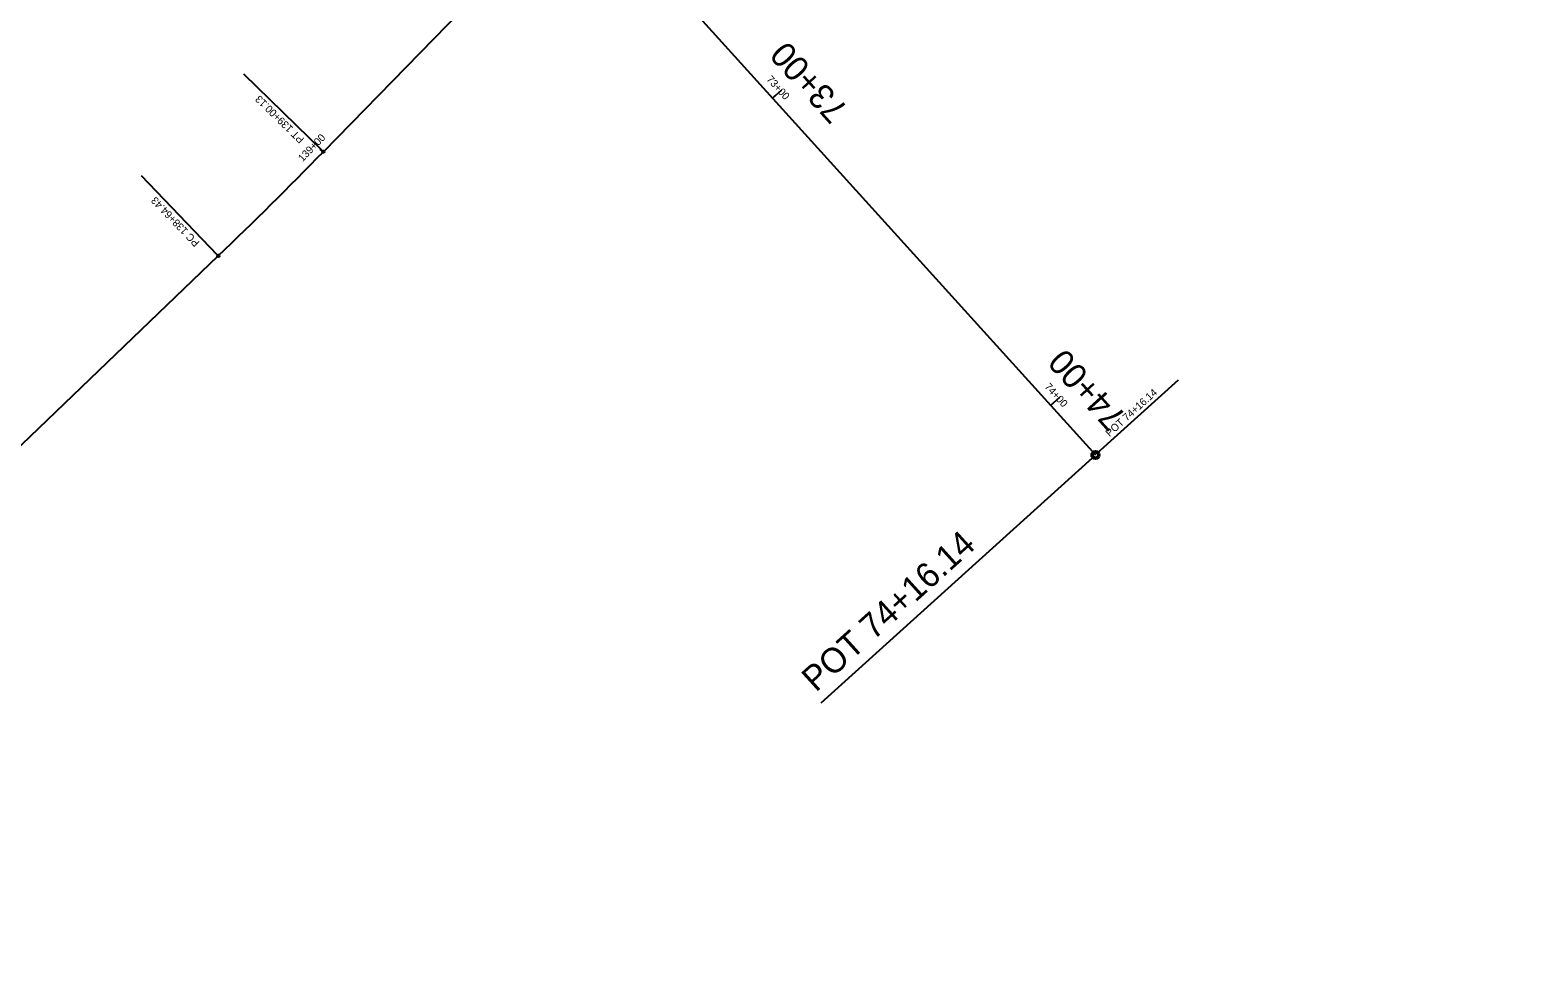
# Model space of a CAD drawing. Extents: x 2252491 to 2257126, y 13788370 to 13792743.
# Drawn here: x 2255321.9 to 2255685.6, y 13791067.5 to 13791291.8 of the extents above; entities that cross this region are included whole.
import ezdxf

# ---------------------------------------------------------------- set-up
doc = ezdxf.new("R2010")
doc.units = 0
for name, color, linetype in [('D_ALIGN_1', 7, 'Continuous'), ('D_ALIGN_ANNO_1', 7, 'Continuous'), ('D_ALIGN_ANNO_DOVE_CROSSING', 7, 'Continuous'), ('D_ALIGN_ANNO_DOVE_CROSSING_30', 7, 'Continuous'), ('D_ALIGN_DOVE_CROSSING', 7, 'Continuous')]:
    doc.layers.add(name, color=color, linetype=linetype)

msp = doc.modelspace()

# ---------------------------------------------------------------- linework, layer by layer
at = {"layer": 'D_ALIGN_1'}
for p, q in [((2255392.67, 13791262.46), (2255685.62, 13791562.66)), ((2255062.92, 13790944.99), (2255367.32, 13791237.32))]:
    msp.add_line(p, q, dxfattribs=at)
msp.add_arc((2254605.4, 13792030.71), 1100, 313.84074, 315.70035, dxfattribs=at)
at = {"layer": 'D_ALIGN_ANNO_1'}
for p, q in [((2255392.45, 13791262.67), (2255373.51, 13791281.15)), ((2255392.58, 13791262.37), (2255391.93, 13791263)), ((2255367.11, 13791237.53), (2255348.78, 13791256.62))]:
    msp.add_line(p, q, dxfattribs=at)
for centre in [(2255392.67, 13791262.46), (2255367.32, 13791237.32)]:
    msp.add_circle(centre, 0.3, dxfattribs=at)
at = {"layer": 'D_ALIGN_ANNO_DOVE_CROSSING'}
for p, q in [((2255501, 13791275.41), (2255503.22, 13791277.42)), ((2255568.08, 13791201.25), (2255570.3, 13791203.26)), ((2255512.78, 13791129.47), (2255578.17, 13791188.61))]:
    msp.add_line(p, q, dxfattribs=at)
msp.add_circle((2255578.91, 13791189.28), 1, dxfattribs=at)
at = {"layer": 'D_ALIGN_ANNO_DOVE_CROSSING_30'}
for p, q in [((2255501, 13791275.41), (2255501.66, 13791276.01)), ((2255579.35, 13791189.68), (2255598.97, 13791207.43)), ((2255568.08, 13791201.25), (2255568.75, 13791201.85))]:
    msp.add_line(p, q, dxfattribs=at)
msp.add_circle((2255578.91, 13791189.28), 0.6, dxfattribs=at)
at = {"layer": 'D_ALIGN_DOVE_CROSSING'}
msp.add_line((2255410.82, 13791375.1), (2255578.91, 13791189.28), dxfattribs=at)

# ---------------------------------------------------------------- texts
at = {"layer": 'D_ALIGN_ANNO_1'}
for s, rotation, p in [('PT 139+00.13', 135.7003, (2255388.17, 13791265.59)), ('139+00', 45.6937, (2255387.65, 13791259.9)), ('PC 138+64.43', 133.8407, (2255362.93, 13791240.59))]:
    msp.add_text(s, height=1.8, rotation=rotation, dxfattribs=at).set_placement(p)
at = {"layer": 'D_ALIGN_ANNO_DOVE_CROSSING'}
for s, rotation, p in [('73+00', 132.1313, (2255519.54, 13791272.8)), ('74+00', 132.1313, (2255586.63, 13791198.63)), ('POT 74+16.14', 42.1313, (2255511.47, 13791131.89))]:
    msp.add_text(s, height=6, rotation=rotation, dxfattribs=at).set_placement(p)
at = {"layer": 'D_ALIGN_ANNO_DOVE_CROSSING_30'}
for s, rotation, p in [('73+00', 312.1313, (2255499.44, 13791279.82)), ('74+00', 312.1313, (2255566.52, 13791205.66)), ('POT 74+16.14', 42.1313, (2255582.31, 13791193.57))]:
    msp.add_text(s, height=1.8, rotation=rotation, dxfattribs=at).set_placement(p)

doc.saveas('drawing.dxf')
